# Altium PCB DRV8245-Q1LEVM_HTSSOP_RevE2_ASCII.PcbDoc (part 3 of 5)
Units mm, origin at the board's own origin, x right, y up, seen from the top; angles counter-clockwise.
Board outline 81.9 x 103.6 mm, 4 copper layers (Top Layer, Signal Layer 1, Signal Layer 2, Bottom Layer), stack 1.554 mm thick; 187 components, 116 nets, 590 pads, 1182 vias.
Unrouted connection lines stored in the file: 116.
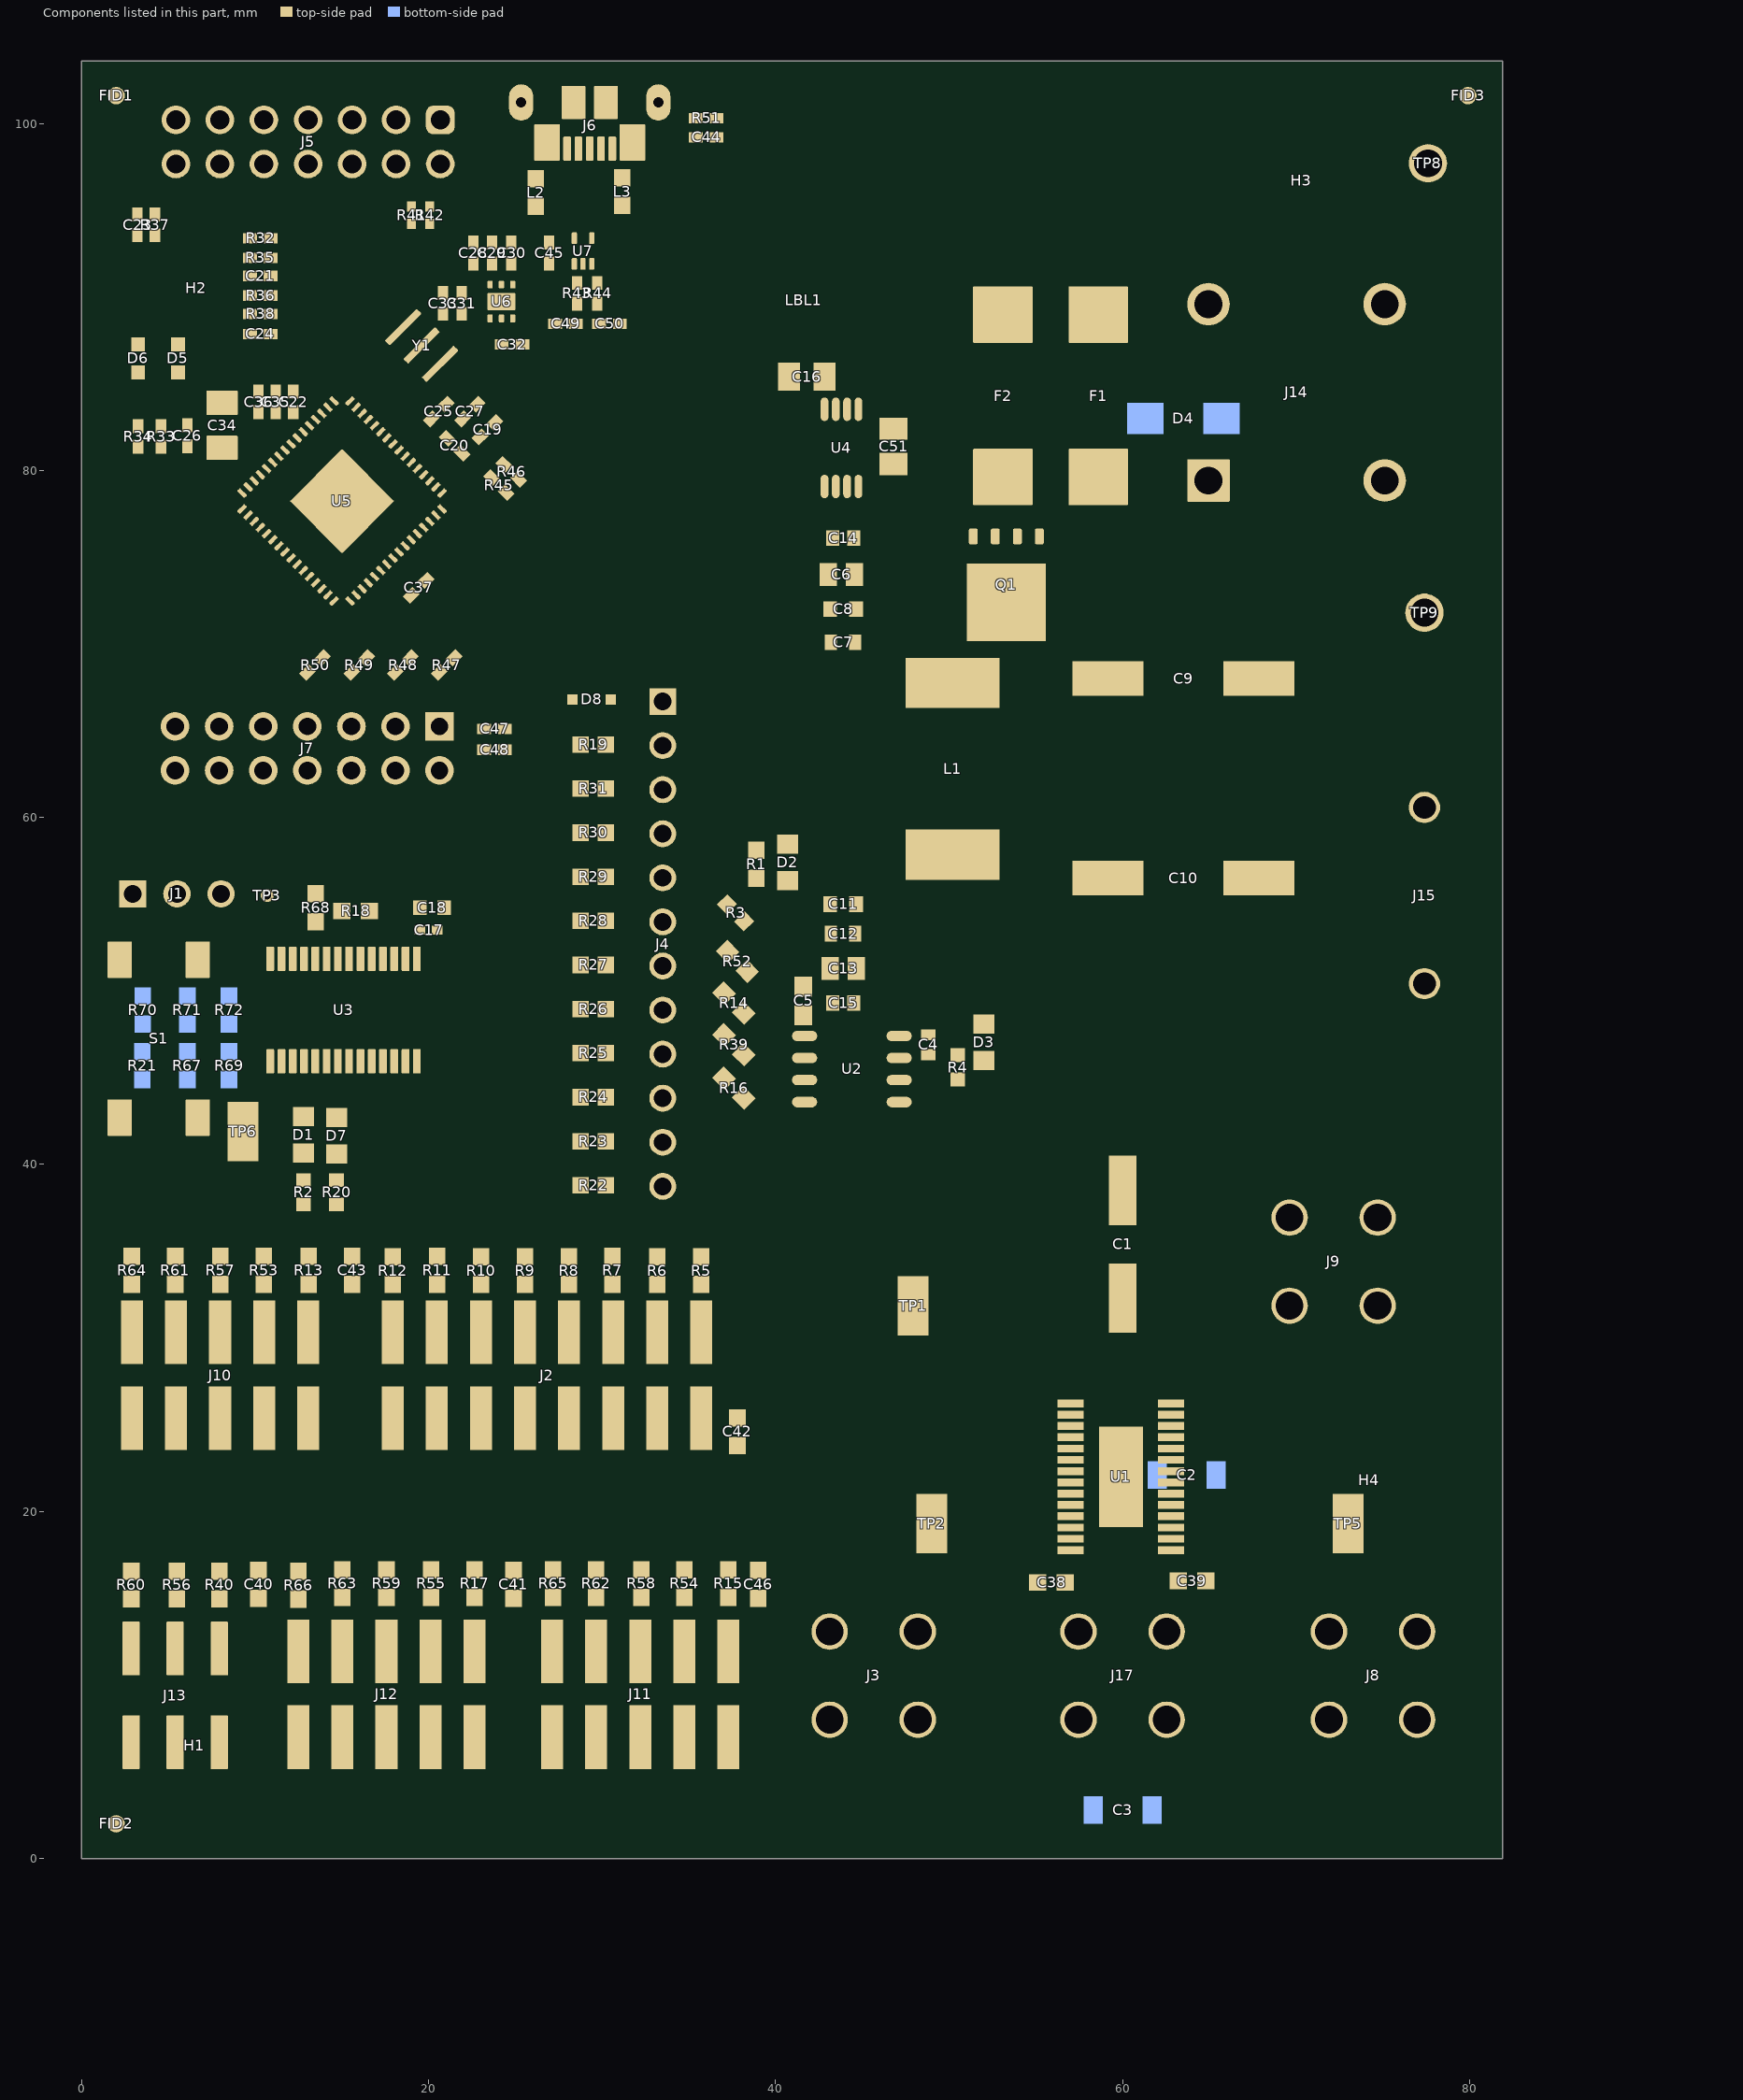
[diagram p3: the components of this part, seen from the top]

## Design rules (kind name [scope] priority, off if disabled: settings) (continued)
PolygonConnect PolygonConnect_69 [All vs IsNamedPolygon('TOP_LAYER_OUT1_P129')] p19: connectstyle=Direct reliefconductorwidth=0.254 reliefentries=4 polygonreliefangle="90 Angle" airgapwidth=0.254
PolygonConnect PolygonConnect_68 [All vs IsNamedPolygon('TOP_LAYER_VM_P085')] p20: connectstyle=Direct reliefconductorwidth=0.254 reliefentries=4 polygonreliefangle="90 Angle" airgapwidth=0.254
PolygonConnect PolygonConnect_67 [All vs IsNamedPolygon('BOTTOM_LAYER_P_IN_P174')] p21: connectstyle=Direct reliefconductorwidth=0.254 reliefentries=4 polygonreliefangle="90 Angle" airgapwidth=0.254
PolygonConnect PolygonConnect_66 [All vs IsNamedPolygon('BOTTOM_LAYER_NETF1_2_P203')] p22: connectstyle=Direct reliefconductorwidth=0.254 reliefentries=4 polygonreliefangle="90 Angle" airgapwidth=0.254
PolygonConnect PolygonConnect_65 [All vs IsNamedPolygon('BOTTOM_LAYER_VBAT_P165')] p23: connectstyle=Direct reliefconductorwidth=0.254 reliefentries=4 polygonreliefangle="90 Angle" airgapwidth=0.254
PolygonConnect PolygonConnect_64 [All vs IsNamedPolygon('TOP_LAYER_VM_P167')] p24: connectstyle=Direct reliefconductorwidth=0.254 reliefentries=4 polygonreliefangle="90 Angle" airgapwidth=0.254
PolygonConnect PolygonConnect_63 [All vs IsNamedPolygon('TOP_LAYER_VM_P167')] p25: connectstyle=Direct reliefconductorwidth=0.254 reliefentries=4 polygonreliefangle="90 Angle" airgapwidth=0.254
PolygonConnect PolygonConnect_62 [All vs IsNamedPolygon('TOP_LAYER_VM_P171')] p26: connectstyle=Direct reliefconductorwidth=0.254 reliefentries=4 polygonreliefangle="90 Angle" airgapwidth=0.254
PolygonConnect PolygonConnect_61 [All vs IsNamedPolygon('SIGNAL_LAYER_2_GND_P199')] p27: connectstyle=Direct reliefconductorwidth=0.254 reliefentries=4 polygonreliefangle="90 Angle" airgapwidth=0.254
PolygonConnect PolygonConnect_60 [All vs IsNamedPolygon('SIGNAL_LAYER_2_NETF1_2_P196')] p28: connectstyle=Direct reliefconductorwidth=0.254 reliefentries=4 polygonreliefangle="90 Angle" airgapwidth=0.254
PolygonConnect PolygonConnect_59 [All vs IsNamedPolygon('SIGNAL_LAYER_2_VBAT_P197')] p29: connectstyle=Direct reliefconductorwidth=0.254 reliefentries=4 polygonreliefangle="90 Angle" airgapwidth=0.254
PolygonConnect PolygonConnect_58 [All vs IsNamedPolygon('SIGNAL_LAYER_2_P_IN_P198')] p30: connectstyle=Direct reliefconductorwidth=0.254 reliefentries=4 polygonreliefangle="90 Angle" airgapwidth=0.254
PolygonConnect PolygonConnect_57 [All vs IsNamedPolygon('SIGNAL_LAYER_2_3V3_P194')] p31: connectstyle=Direct reliefconductorwidth=0.254 reliefentries=4 polygonreliefangle="90 Angle" airgapwidth=0.254
PolygonConnect PolygonConnect_56 [All vs IsNamedPolygon('TOP_LAYER_NETF1_2_P207')] p32: connectstyle=Direct reliefconductorwidth=0.254 reliefentries=4 polygonreliefangle="90 Angle" airgapwidth=0.254
PolygonConnect PolygonConnect_55 [All vs IsNamedPolygon('TOP_LAYER_VBAT_P223')] p33: connectstyle=Direct reliefconductorwidth=0.254 reliefentries=4 polygonreliefangle="90 Angle" airgapwidth=0.254
PolygonConnect PolygonConnect_54 [All vs IsNamedPolygon('TOP_LAYER_P_IN_P227')] p34: connectstyle=Direct reliefconductorwidth=0.254 reliefentries=4 polygonreliefangle="90 Angle" airgapwidth=0.254
PolygonConnect PolygonConnect_53 [All vs IsNamedPolygon('TOP_LAYER_GND_P086')] p35: connectstyle=Direct reliefconductorwidth=0.254 reliefentries=4 polygonreliefangle="90 Angle" airgapwidth=0.254
PolygonConnect PolygonConnect_52 [All vs IsNamedPolygon('SIGNAL_LAYER_2_VM_P177') Or  IsNamedPolygon('SIGNAL_LAYER_2_VM_P179') Or  IsNamedPolygon('SIGNAL_LAYER_2_VM_P160') Or  IsNamedPolygon('SIGNAL_LAYER_2_VM_P175') Or  IsNamedPolygon('SIGNAL_LAYER_2_VM_P181')] p36: connectstyle=Direct reliefconductorwidth=0.254 reliefentries=4 polygonreliefangle="90 Angle" airgapwidth=0.254
PolygonConnect PolygonConnect_51 [All vs IsNamedPolygon('SIGNAL_LAYER_2_EZFET_VBUS_P136')] p37: connectstyle=Direct reliefconductorwidth=0.254 reliefentries=4 polygonreliefangle="90 Angle" airgapwidth=0.254
PolygonConnect PolygonConnect_50 [All vs IsNamedPolygon('SIGNAL_LAYER_2_EZFET_VCC_P132')] p38: connectstyle=Direct reliefconductorwidth=0.254 reliefentries=4 polygonreliefangle="90 Angle" airgapwidth=0.254
PolygonConnect PolygonConnect_49 [All vs IsNamedPolygon('SIGNAL_LAYER_2_3V3_MCU_P192')] p39: connectstyle=Direct reliefconductorwidth=0.254 reliefentries=4 polygonreliefangle="90 Angle" airgapwidth=0.254
PolygonConnect PolygonConnect_48 [All vs IsNamedPolygon('SIGNAL_LAYER_1_GND_P190')] p40: connectstyle=Direct reliefconductorwidth=0.254 reliefentries=4 polygonreliefangle="90 Angle" airgapwidth=0.254
PolygonConnect PolygonConnect_47 [All vs IsNamedPolygon('SIGNAL_LAYER_1_GND_P184')] p41: connectstyle=Direct reliefconductorwidth=0.254 reliefentries=4 polygonreliefangle="90 Angle" airgapwidth=0.254
PolygonConnect PolygonConnect_46 [All vs IsNamedPolygon('BOTTOM_LAYER_GND_P241')] p42: connectstyle=Direct reliefconductorwidth=0.254 reliefentries=4 polygonreliefangle="90 Angle" airgapwidth=0.254
PolygonConnect PolygonConnect_45 [All vs IsNamedPolygon('BOTTOM_LAYER_GND_P241')] p43: connectstyle=Direct reliefconductorwidth=0.254 reliefentries=4 polygonreliefangle="90 Angle" airgapwidth=0.254
PolygonConnect PolygonConnect_44 [All vs IsNamedPolygon('BOTTOM_LAYER_OUT2_P163')] p44: connectstyle=Direct reliefconductorwidth=0.254 reliefentries=4 polygonreliefangle="90 Angle" airgapwidth=0.254
PolygonConnect PolygonConnect_43 [All vs IsNamedPolygon('BOTTOM_LAYER_VM_P166')] p45: connectstyle=Direct reliefconductorwidth=0.254 reliefentries=4 polygonreliefangle="90 Angle" airgapwidth=0.254
PolygonConnect PolygonConnect_42 [All vs IsNamedPolygon('BOTTOM_LAYER_VM_P235')] p46: connectstyle=Direct reliefconductorwidth=0.254 reliefentries=4 polygonreliefangle="90 Angle" airgapwidth=0.254
PolygonConnect PolygonConnect_41 [All vs IsNamedPolygon('BOTTOM_LAYER_OUT1_P164')] p47: connectstyle=Direct reliefconductorwidth=0.254 reliefentries=4 polygonreliefangle="90 Angle" airgapwidth=0.254
PolygonConnect PolygonConnect_40 [All vs IsNamedPolygon('BOTTOM_LAYER_GND_P162')] p48: connectstyle=Direct reliefconductorwidth=0.254 reliefentries=4 polygonreliefangle="90 Angle" airgapwidth=0.254
PolygonConnect PolygonConnect_39 [All vs IsNamedPolygon('SIGNAL_LAYER_2_VM_P160')] p49: connectstyle=Direct reliefconductorwidth=0.254 reliefentries=4 polygonreliefangle="90 Angle" airgapwidth=0.254
PolygonConnect PolygonConnect_38 [All vs IsNamedPolygon('SIGNAL_LAYER_2_NONET_P138')] p50: connectstyle=Direct reliefconductorwidth=0.254 reliefentries=4 polygonreliefangle="90 Angle" airgapwidth=0.254
PolygonConnect PolygonConnect_37 [All vs IsNamedPolygon('SIGNAL_LAYER_1_VM_P146')] p51: connectstyle=Direct reliefconductorwidth=0.254 reliefentries=4 polygonreliefangle="90 Angle" airgapwidth=0.254
PolygonConnect PolygonConnect_36 [All vs IsNamedPolygon('SIGNAL_LAYER_2_GND_P156')] p52: connectstyle=Direct reliefconductorwidth=0.254 reliefentries=4 polygonreliefangle="90 Angle" airgapwidth=0.254
PolygonConnect PolygonConnect_35 [All vs IsNamedPolygon('BOTTOM_LAYER_EZFET_USB_SHIELD_P219')] p53: connectstyle=Direct reliefconductorwidth=0.254 reliefentries=4 polygonreliefangle="90 Angle" airgapwidth=0.254
PolygonConnect PolygonConnect_34 [All vs IsNamedPolygon('SIGNAL_LAYER_1_VM_P144')] p54: connectstyle=Direct reliefconductorwidth=0.254 reliefentries=4 polygonreliefangle="90 Angle" airgapwidth=0.254
PolygonConnect PolygonConnect_33 [All vs IsNamedPolygon('SIGNAL_LAYER_1_VM_P148') Or  IsNamedPolygon('SIGNAL_LAYER_1_VM_P148')] p55: connectstyle=Direct reliefconductorwidth=0.254 reliefentries=4 polygonreliefangle="90 Angle" airgapwidth=0.254
PolygonConnect PolygonConnect_32 [All vs IsNamedPolygon('SIGNAL_LAYER_1_GND_P154')] p56: connectstyle=Direct reliefconductorwidth=0.254 reliefentries=4 polygonreliefangle="90 Angle" airgapwidth=0.254
PolygonConnect PolygonConnect_31 [All vs IsNamedPolygon('SIGNAL_LAYER_2_NONET_P138')] p57: connectstyle=Direct reliefconductorwidth=0.254 reliefentries=4 polygonreliefangle="90 Angle" airgapwidth=0.254
PolygonConnect PolygonConnect_30 [All vs IsNamedPolygon('SIGNAL_LAYER_2_GND_P082')] p58: connectstyle=Direct reliefconductorwidth=0.254 reliefentries=4 polygonreliefangle="90 Angle" airgapwidth=0.254
PolygonConnect PolygonConnect_29 [All vs IsNamedPolygon('TOP_LAYER_GND_P076')] p59: connectstyle=Direct reliefconductorwidth=0.254 reliefentries=4 polygonreliefangle="90 Angle" airgapwidth=0.254
PolygonConnect PolygonConnect_28 [All vs IsNamedPolygon('TOP_LAYER_GND_P087')] p60: connectstyle=Direct reliefconductorwidth=0.254 reliefentries=4 polygonreliefangle="90 Angle" airgapwidth=0.254
PolygonConnect PolygonConnect_27 [All vs IsNamedPolygon('TOP_LAYER_VM_P127') Or  IsNamedPolygon('TOP_LAYER_VM_P085')] p61: connectstyle=Direct reliefconductorwidth=0.254 reliefentries=4 polygonreliefangle="90 Angle" airgapwidth=0.254
PolygonConnect PolygonConnect_26 [All vs IsNamedPolygon('TOP_LAYER_GND_P117')] p62: connectstyle=Direct reliefconductorwidth=0.254 reliefentries=4 polygonreliefangle="90 Angle" airgapwidth=0.254
PolygonConnect PolygonConnect_25 [All vs IsNamedPolygon('TOP_LAYER_OUT1_P129') Or  IsNamedPolygon('TOP_LAYER_OUT2_P173')] p63: connectstyle=Direct reliefconductorwidth=0.254 reliefentries=4 polygonreliefangle="90 Angle" airgapwidth=0.254
PolygonConnect PolygonConnect_24 [All vs IsNamedPolygon('SIGNAL_LAYER_2_NONET_P113')] p64: connectstyle=Direct reliefconductorwidth=0.254 reliefentries=4 polygonreliefangle="90 Angle" airgapwidth=0.254
PolygonConnect PolygonConnect_23 [All vs IsNamedPolygon('BOTTOM_LAYER_NONET_P115')] p65: connectstyle=Direct reliefconductorwidth=0.254 reliefentries=4 polygonreliefangle="90 Angle" airgapwidth=0.254
PolygonConnect PolygonConnect_22 [All vs IsNamedPolygon('SIGNAL_LAYER_1_NONET_P111')] p66: connectstyle=Direct reliefconductorwidth=0.254 reliefentries=4 polygonreliefangle="90 Angle" airgapwidth=0.254
PolygonConnect PolygonConnect_21 [All vs IsNamedPolygon('TOP_LAYER_NONET_P083')] p67: connectstyle=Direct reliefconductorwidth=0.254 reliefentries=4 polygonreliefangle="90 Angle" airgapwidth=0.254
PolygonConnect PolygonConnect_20 [All vs IsNamedPolygon('TOP_LAYER_NONET_P105')] p68: connectstyle=Direct reliefconductorwidth=0.254 reliefentries=4 polygonreliefangle="90 Angle" airgapwidth=0.254
PolygonConnect PolygonConnect_19 [All vs IsNamedPolygon('TOP_LAYER_OUT2_P107')] p69: connectstyle=Direct reliefconductorwidth=0.254 reliefentries=4 polygonreliefangle="90 Angle" airgapwidth=0.254
PolygonConnect PolygonConnect_18 [All vs IsNamedPolygon('TOP_LAYER_NONET_P101')] p70: connectstyle=Direct reliefconductorwidth=0.254 reliefentries=4 polygonreliefangle="90 Angle" airgapwidth=0.254
PolygonConnect PolygonConnect_17 [All vs IsNamedPolygon('TOP_LAYER_OUT1_P103')] p71: connectstyle=Direct reliefconductorwidth=0.254 reliefentries=4 polygonreliefangle="90 Angle" airgapwidth=0.254
PolygonConnect PolygonConnect_16 [All vs IsNamedPolygon('TOP_LAYER_OUT1_P000')] p72: connectstyle=Direct reliefconductorwidth=0.254 reliefentries=4 polygonreliefangle="90 Angle" airgapwidth=0.254
PolygonConnect PolygonConnect_15 [All vs IsNamedPolygon('TOP_LAYER_NONET_P093')] p73: connectstyle=Direct reliefconductorwidth=0.254 reliefentries=4 polygonreliefangle="90 Angle" airgapwidth=0.254
PolygonConnect PolygonConnect_14 [All vs IsNamedPolygon('TOP_LAYER_OUT2_P099')] p74: connectstyle=Direct reliefconductorwidth=0.254 reliefentries=4 polygonreliefangle="90 Angle" airgapwidth=0.254
PolygonConnect PolygonConnect_13 [All vs IsNamedPolygon('TOP_LAYER_OUT1_P000')] p75: connectstyle=Direct reliefconductorwidth=0.254 reliefentries=4 polygonreliefangle="90 Angle" airgapwidth=0.254
PolygonConnect PolygonConnect_12 [All vs IsNamedPolygon('BOTTOM_LAYER_NONET_P079') Or  IsNamedPolygon('SIGNAL_LAYER_2_NONET_P078') Or  IsNamedPolygon('SIGNAL_LAYER_1_NONET_P077') Or  IsNamedPolygon('TOP_LAYER_NONET_P083') Or  IsNamedPolygon('BOTTOM_LAYER_NONET_P072') Or  IsNamedPolygon('SIGNAL_LAYER_2_NONET_P070') Or  IsNamedPolygon('SIGNAL_LAYER_1_NONET_P059') Or  IsNamedPolygon('TOP_LAYER_OUT2_P058') Or  IsNamedPolygon('BOTTOM_LAYER_NONET_P056') Or  IsNamedPolygon('SIGNAL_LAYER_2_NONET_P054') Or  IsNamedPolygon('SIGNAL_LAYER_1_NONET_P052') Or  IsNamedPolygon('TOP_LAYER_OUT1_P050') Or  IsNamedPolygon('BOTTOM_LAYER_VM_P044') Or  IsNamedPolygon('SIGNAL_LAYER_2_VM_P042') Or  IsNamedPolygon('SIGNAL_LAYER_1_VM_P040') Or  IsNamedPolygon('TOP_LAYER_VM_P038') Or  IsNamedPolygon('BOTTOM_LAYER_VM_P036') Or  IsNamedPolygon('SIGNAL_LAYER_2_VM_P018') Or  IsNamedPolygon('SIGNAL_LAYER_1_VM_P016') Or  IsNamedPolygon('TOP_LAYER_VM_P002')] p76: connectstyle=Direct reliefconductorwidth=0.254 reliefentries=4 polygonreliefangle="90 Angle" airgapwidth=0.254
PolygonConnect PolygonConnect_11 [All vs IsNamedPolygon('TOP_LAYER_NONET_P089') Or  IsNamedPolygon('TOP_LAYER_NONET_P090')] p77: connectstyle=Direct reliefconductorwidth=0.254 reliefentries=4 polygonreliefangle="90 Angle" airgapwidth=0.254
PolygonConnect PolygonConnect_10 [All vs IsNamedPolygon('BOTTOM_LAYER_EZFET_USB_SHIELD_P002') Or  IsNamedPolygon('TOP_LAYER_EZFET_USB_SHIELD_P201') Or  IsNamedPolygon('SIGNAL_LAYER_2_EZFET_VBUS_P018') Or  IsNamedPolygon('SIGNAL_LAYER_2_EZFET_VCC_P016')] p78: connectstyle=Direct reliefconductorwidth=0.254 reliefentries=4 polygonreliefangle="90 Angle" airgapwidth=0.254
PolygonConnect PolygonConnect_9 [All vs IsNamedPolygon('TOP_LAYER_VM_P123') Or  IsNamedPolygon('TOP_LAYER_VM_P123') Or  IsNamedPolygon('TOP_LAYER_VM_P123')] p79: connectstyle=Direct reliefconductorwidth=0.254 reliefentries=4 polygonreliefangle="90 Angle" airgapwidth=0.254
PolygonConnect PolygonConnect_8 [All vs IsNamedPolygon('TOP_LAYER_NONET_P072')] p80: connectstyle=Direct reliefconductorwidth=0.254 reliefentries=4 polygonreliefangle="90 Angle" airgapwidth=0.254
PolygonConnect PolygonConnect_7 [All vs IsNamedPolygon('TOP_LAYER_NONET_P072')] p81: connectstyle=Direct reliefconductorwidth=0.254 reliefentries=4 polygonreliefangle="90 Angle" airgapwidth=0.254
PolygonConnect PolygonConnect_6 [All vs IsNamedPolygon('TOP_LAYER_VM_P042')] p82: connectstyle=Direct reliefconductorwidth=0.254 reliefentries=4 polygonreliefangle="90 Angle" airgapwidth=0.254
PolygonConnect PolygonConnect_5 [All vs IsNamedPolygon('TOP_LAYER_VM_P044')] p83: connectstyle=Direct reliefconductorwidth=0.254 reliefentries=4 polygonreliefangle="90 Angle" airgapwidth=0.254
PolygonConnect PolygonConnect_4 [All vs IsNamedPolygon('TOP_LAYER_VM_P046')] p84: connectstyle=Direct reliefconductorwidth=0.254 reliefentries=4 polygonreliefangle="90 Angle" airgapwidth=0.254
PolygonConnect PolygonConnect_3 [All vs IsNamedPolygon('TOP_LAYER_GND_P036') Or  IsNamedPolygon('TOP_LAYER_OUT2_P040') Or  IsNamedPolygon('TOP_LAYER_OUT1_P038')] p85: connectstyle=Direct reliefconductorwidth=0.254 reliefentries=4 polygonreliefangle="90 Angle" airgapwidth=0.254
PolygonConnect PolygonConnect_2 [InNet('EZFET_VBUS') vs IsNamedPolygon('TOP_LAYER_EZFET_VBUS_P008')] p86: connectstyle=Direct reliefconductorwidth=0.254 reliefentries=4 polygonreliefangle="90 Angle" airgapwidth=0.254
PolygonConnect PolygonConnect_1 [InNetClass('Power-Net') vs IsNamedPolygon('TOP_LAYER_EZFET_USB_SHIELD_P201')] p87: connectstyle=Direct reliefconductorwidth=0.254 reliefentries=4 polygonreliefangle="90 Angle" airgapwidth=0.254
PolygonConnect [All] p88: connectstyle=Relief reliefconductorwidth=0.254 reliefentries=4 polygonreliefangle="90 Angle" airgapwidth=0.254
RoutingCorners [All] p0: scope1count=1 scope1_0_kind=Board scope1_0_value=Board scope2count=1 scope2_0_kind=Board scope2_0_value=Board commentlength=0 cornerstyle=45-Degree minsetback=2.54 maxsetback=2.54
RoutingLayers [All] p0: scope1count=1 scope1_0_kind=Board scope1_0_value=Board scope2count=1 scope2_0_kind=Board scope2_0_value=Board commentlength=0 top layer=Automatic mid layer 1=Automatic mid layer 2=Automatic bottom layer=Automatic
RoutingPriority [All] p0: scope1count=1 scope1_0_kind=Board scope1_0_value=Board scope2count=1 scope2_0_kind=Board scope2_0_value=Board commentlength=0
RoutingTopology [All] p0: scope1count=1 scope1_0_kind=Board scope1_0_value=Board scope2count=1 scope2_0_kind=Board scope2_0_value=Board commentlength=0 topology=Shortest
RoutingVias [All] p0: scope1count=1 scope1_0_kind=Board scope1_0_value=Board scope2count=1 scope2_0_kind=Board scope2_0_value=Board commentlength=0 holewidth=0.406 width=0.864 viastyle="Through Hole" minholewidth=0.2 minwidth=0.66 maxholewidth=1.016 maxwidth=1.651
RoutingVias ThermalPadVias [All] p0 off: scope1count=1 scope1_0_kind=Board scope1_0_value=Board scope2count=1 scope2_0_kind=Board scope2_0_value=Board commentlength=63 holewidth=0.2 width=0.5 viastyle="Through Hole" minholewidth=0.2 minwidth=0.5 maxholewidth=0.33 maxwidth=0.6 // Protel DXP Scope 1 Expression Was: IsVia and InAnyComponent
RoutingVias ThermalPadVias [IsVia and InAnyComponent] p1: holewidth=0.2 width=0.5 viastyle="Through Hole" minholewidth=0.2 minwidth=0.5 maxholewidth=0.33 maxwidth=0.6
RoutingVias [All] p2: holewidth=0.406 width=0.864 viastyle="Through Hole" minholewidth=0.2 minwidth=0.66 maxholewidth=1.016 maxwidth=1.651
ShortCircuit [All] p0: scope1count=1 scope1_0_kind=Board scope1_0_value=Board scope2count=1 scope2_0_kind=Board scope2_0_value=Board commentlength=0 allowed=FALSE
SilkToBoardRegionClearance [All] p0 off: scope1count=1 scope1_0_kind=Board scope1_0_value=Board scope2count=1 scope2_0_kind=Board scope2_0_value=Board commentlength=130 // Protel DXP Scope 1 Expression Was: Not ((IsComment or IsDesignator) And (Hide <> 'False')) and not InRegion(1000,500,4000,800)
SilkToBoardRegionClearance [Not ((IsComment or IsDesignator) And (Hide <> 'False')) and not InRegion(1000,500,4000,800)] p1:
SilkToSilkClearance [All] p0: scope1count=1 scope1_0_kind=Board scope1_0_value=Board scope2count=1 scope2_0_kind=Board scope2_0_value=Board commentlength=0
SilkToSilkClearance SilkToSilkClearance_Pb-FreeLogo [All] p0 off: scope1count=1 scope1_0_kind=Board scope1_0_value=Board scope2count=1 scope2_0_kind=Board scope2_0_value=Board commentlength=120 // Protel DXP Scope 2 Expression Was: (HasFootprint('Pb-Free_Overlay_Medium') OR HasFootprint('Pb-Free_Overlay_Small'))
SilkToSilkClearance SilkToSilkClearance_Pb-FreeLogo [(HasFootprint('Pb-Free_Overlay_Medium') OR HasFootprint('Pb-Free_Overlay_Small')) vs (HasFootprint('Pb-Free_Overlay_Medium') OR HasFootprint('Pb-Free_Overlay_Small'))] p1: silktosilkclearance=0
SilkToSilkClearance [All] p2: silktosilkclearance=0.1
SilkToSolderMaskClearance "Silk to Solder Mask Opening" [All] p0: scope1count=1 scope1_0_kind=Board scope1_0_value=Board scope2count=1 scope2_0_kind=Board scope2_0_value=Board commentlength=0
SilkToSolderMaskClearance SilkToComponentPadClearance [All] p0 off: scope1count=1 scope1_0_kind=Board scope1_0_value=Board scope2count=1 scope2_0_kind=Board scope2_0_value=Board commentlength=87 // Protel DXP Scope 1 Expression Was: (IsPad or IsFill or IsRegion) and InAnycomponent
SilkToSolderMaskClearance SilkToComponentPadClearance [(IsPad or IsFill or IsRegion) and InAnycomponent] p1: minsilkscreentomaskgap=0.127 clearancetoexposedcopper=TRUE
SilkToSolderMaskClearance "Silk to Solder Mask Opening" [All] p2: minsilkscreentomaskgap=0.1 clearancetoexposedcopper=FALSE
SolderMaskExpansion [All] p0: scope1count=1 scope1_0_kind=Board scope1_0_value=Board scope2count=1 scope2_0_kind=Board scope2_0_value=Board commentlength=0 expansion=0.05
SolderMaskExpansion [All] p1: expansion=0.05
UnRoutedNet [All] p0: scope1count=1 scope1_0_kind=Board scope1_0_value=Board scope2count=1 scope2_0_kind=Board scope2_0_value=Board commentlength=0
UnRoutedNet [All] p1: checkbadconnections=TRUE
UnpouredPolygon [All] p0: scope1count=1 scope1_0_kind=Board scope1_0_value=Board scope2count=1 scope2_0_kind=Board scope2_0_value=Board commentlength=0
Width [All] p0: scope1count=1 scope1_0_kind=Board scope1_0_value=Board scope2count=1 scope2_0_kind=Board scope2_0_value=Board commentlength=0 maxlimit=2.54 minlimit=0.152 preferedwidth=0.254
Width [All] p1: maxlimit=2.54 minlimit=0.152 preferedwidth=0.254 checkconnectedcopper=TRUE
14 further rules are at their usual default settings.

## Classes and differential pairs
net class Power-Net: 3V3_MCU EZFET_VBUS EZFET_VCC GND
component class Header: J2 J4 J5 J7 J10 J11 J12 J13
component class ezFET: C19 C20 C21 C22 C23 C24 C25 C26 C27 C28 C29 C30 C31 C32 C33 C34 C35 C36 C37 C44 C45 C47 C48 C49 C50 D5 D6 J5 J6 J7 L2 L3 R32 R33 R34 R35 R36 R37 R38 R41 R42 R43 R44 R45 R46 R47 R48 R49 R50 R51 U5 U6 U7 Y1
component class Logo: Logo2
component class FiducialMark: FID1 FID2 FID3
component class AssemblyNote: ZZ1 ZZ2 ZZ3 ZZ4
component class Label: LBL1
differential pair USB_D: +USB_D_P -USB_D_N
differential pair " ": +EZFET_D_P -EZFET_D_N

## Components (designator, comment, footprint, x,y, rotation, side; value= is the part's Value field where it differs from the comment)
C1 "EEE-2AA100UP" SM_RADIAL_E 60,35.4 r270 top
C2 "C3216X7R2A104K160AA" 1206_180 63.7,22.1 r180 bottom
C3 "C3216X7R2A104K160AA" 1206_180 60,2.8 r0 bottom
C4 "CL10B104JB8NNNC" FP-CL10-0_1-MFG 48.8,46.9 r270 top
C5 "CL10A226MQ8NUNE" FP-CL10-IPC_A 41.6,49.427 r90 top
C6 "1uF" CAPC2013X135X45LL10T25 43.8,74 r0 top
C7 "0.1uF" CAPC0603(1608)100_L 43.9,70.1 r0 top
C8 "CC0603KPX7R9BB103" FP-CC0603-DA-MFG 43.9,72 r0 top
C9 "EEE-FK1H151P" SM_RADIAL_G 63.5,68 r0 top
C10 "EEE-FK1H151P" SM_RADIAL_G 63.5,56.5 r0 top
C11 "CC0603KPX7R9BB103" FP-CC0603-DA-MFG 43.9,55 r180 top
C12 "0.1uF" CAPC0603(1608)100_L 43.9,53.3 r0 top
C13 "1uF" CAPC2013X135X45LL10T25 43.9,51.3 r0 top
C14 "1nF" FP-C0603C-CF-MFG#1 44,76.1 r180 top
C15 "1nF" FP-C0603C-CF-MFG#2 43.9,49.3 r180 top
C16 "08055A101JAT2A" 0805_HV 41.8,85.4 r180 top
C17 "Capacitor" 0402_065L 20,53.5 r0 top
C18 "885012206020" 0603L 20.2,54.8 r0 top
C19 "C1005X5R1A475M050BC" 0402 23.397,82.347 r45 top
C20 "GRM155R61A104KA01D" 0402 21.501,81.429 r315 top
C21 "C1005C0G1H330J050BA" 0402 10.302,91.208 r180 top
C22 "GRM155R61A104KA01D" 0402 12.2,83.95 r90 top
C23 "GRM155R71H102KA01D" 0402 3.228,94.149 r270 top
C24 "C1005C0G1H330J050BA" 0402 10.302,87.856 r180 top
C25 "GRM155R61A224KE19D" 0402 20.583,83.39 r45 top
C26 "GRM155R61C474KE01" 0402 6.1,82 r90 top
C27 "GRM155R61A224KE19D" 0402 22.382,83.39 r45 top
C28 "885012105012" 0402 22.577,92.525 r90 top
C29 "GRM155R61A104KA01D" 0402 23.655,92.525 r90 top
C30 "GRM155R71C103KA01D" 0402 24.774,92.525 r90 top
C31 "2.2uF" 0402 21.905,89.625 r90 top
C32 "GRM155R71C103KA01D" 0402 24.814,87.256 r0 top
C33 "885012105012" 0402 20.831,89.625 r90 top
C34 "T520A106M010ATE080" 3216-18 8.1,82.6 r90 top
C35 "GRM155R61A104KA01D" 0402 11.19,83.95 r90 top
C36 "GRM155R61A104KA01D" 0402 10.205,83.95 r90 top
C37 "GRM155R61A104KA01D" 0402 19.43,73.233 r225 top
C38 "CGA3E2X7R2A102K080AA" 0603 55.9,15.9 r180 top
C39 "CGA3E2X7R2A102K080AA" 0603 64,16 r0 top
C40 "CGA3E2X7R2A102K080AA" 0603 10.2,15.8 r270 top
C41 "CGA3E2X7R2A102K080AA" 0603 24.9,15.8 r270 top
C42 "CGA3E2X7R2A102K080AA" 0603 37.8,24.6 r90 top
C43 "CGA3E2X7R2A102K080AA" 0603 15.6,33.9 r270 top
C44 "GRM155R61A224KE19D" 0402 36,99.2 r0 top
C45 "GRM155R61A104KA01D" 0402 26.955,92.525 r90 top
C46 "CGA3E2X7R2A102K080AA" 0603 39,15.8 r270 top
C47 "GRM1555C1H100FA01D" 0402 23.8,65.1 r180 top
C48 "GRM1555C1H100FA01D" 0402 23.8,63.9 r180 top
C49 "GRM1555C1H100FA01D" 0402 27.891,88.458 r180 top
C50 "GRM1555C1H100FA01D" 0402 30.429,88.458 r0 top
C51 "C2012X5R1H225K125AB" 0805_HV 46.8,81.384 r90 top
D1 "150080VS75000" 0805_A 12.8,41.7 r90 top
D2 "150080SS75000" 0805_A 40.7,57.4 r90 top
D3 "150080VS75000" 0805_A 52,47.05 r90 top
D4 "SMAJ36CA" FP-SMAJ-CA-MFG 63.5,83 r180 bottom
D5 "150060RS75000" WL-SMCW_RED 5.561,86.456 r270 top
D6 "CMP-0002894-2" WL-SMCW_GREEN 3.258,86.456 r270 top
D7 "150080VS75000" 0805_A 14.7,41.65 r90 top
D8 "BAT165E6327HTSA1" SOD-323 29.4,66.8 r180 top
F1 "0463030.ER" Fuse_0463 58.6,84.3 r90 top
F2 "0463030.ER" Fuse_0463 53.1,84.3 r90 top
FID1 "Fiducial" Fiducial10-20 2,101.6 r0 top
FID2 "Fiducial" Fiducial10-20 2,2 r90 top
FID3 "Fiducial" Fiducial10-20 79.9,101.6 r0 top
H1 "SJ-5303 (CLEAR)" Bumpon_SJ5003Transparent 6.5,6.5 r0 bottom
H2 "SJ-5303 (CLEAR)" Bumpon_SJ5003Transparent 6.6,90.5 r0 bottom
H3 "SJ-5303 (CLEAR)" Bumpon_SJ5003Transparent 70.3,96.7 r0 bottom
H4 "SJ-5303 (CLEAR)" Bumpon_SJ5003Transparent 74.2,21.8 r180 bottom
J1 "PR20203VBNN" FP-PR20203VBNN-MFG 5.5,55.6 r0 top
J2 "TSM-108-01-L-DV" Samtec_TSM-108-01-x-DV 26.832,27.851 r270 top
J3 "CT3151SP-2" CTE_CT3151SP-2 45.66,-10.898 r90 top
J4 "PBC12SABN" Sullins_PxC12SABN 33.5,52.71 r270 top
J5 "61301421121" Wurth_61301421121 13.056,98.93 r270 top
J6 "CMP-0055311-1" Molex_1051640001 29.291,102.654 r180 top
J7 "PEC07DAAN" CONN_PEC07DAAN 13.015,63.978 r180 top
J8 "CT3151SP-2" CTE_CT3151SP-2 74.44,-10.898 r90 top
J9 "CT3151SP-2" CTE_CT3151SP-2 93.6,34.4 r180 top
J10 "TSM-105-01-L-DV-P" Samtec_TSM-105-01-x-DV 7.99,27.851 r270 top
J11 "TSM-105-01-L-DV-P" Samtec_TSM-105-01-x-DV 32.204,9.465 r270 top
J12 "TSM-105-01-L-DV-P" Samtec_TSM-105-01-x-DV 17.577,9.465 r270 top
J13 "61000621121" Wurth_61000621121 5.4,9.4 r270 top
J14 "691256610002" FP-691256610002_HDR2-MFG 72.5,84.5 r90 top
J15 "D3082-05" Harwin_D3082-05 77.4,55.5 r90 top
J17 "CT3151SP-0" CTE_CT3151SP-0 60,-10.898 r90 top
L1 "1uH" WE-HCC-1210 50.2,62.8 r270 top
L2 "BLM18AG151BH1D" 0603 26.174,96.01 r270 top
L3 "BLM18AG151BH1D" 0603 31.154,96.066 r270 top
LBL1 "THT-14-423-10" Label_650x200 41.6,89.8 r0 top
Logo1 "CE Mark" CE_Mark_5mm 33.6,84 r180 bottom
Logo2 "Texas Instruments" TI_Stacked_Overlay_Small 55.2,99 r0 top
Logo3 "FCC disclaimer" FCC_disclaimer -79.62,84.1 r270 bottom
Logo4 "WEEE logo" WEEE_Minimum 33.7,76.8 r180 bottom
Logo5 "CAUTION.  READ USER GUIDE BEFORE USE" IEC_Caution_Small 60.4,47.9 r0 top
LOGO6 "CAUTION HOT SURFACE" IEC_HotSurface_Small 52.2,26.1 r0 top
Q1 "CSD18513Q5A" DQJ0008A 53.3,73.4 r270 top
R1 "RC0603JR-0710KL" 0603 38.9,57.3 r90 top
R2 "CMP-0025785-4" 0603L 12.8,38.4 r90 top
R3 "CMP-0025785-4" 0603L 37.7,54.5 r315 top
R4 "CRCW06034K99FKEAC" 0603L 50.5,45.6 r270 top
R5 "RC0603FR-07470RL" 0603 35.722,33.882 r270 top
R6 "RC0603FR-07680RL" 0603 33.182,33.882 r270 top
R7 "RC0603FR-071KL" 0603 30.6,33.9 r270 top
R8 "RC0603FR-071K5L" 0603 28.102,33.882 r270 top
R9 "RC0603FR-072K2L" 0603 25.562,33.882 r270 top
R10 "RC0603FR-073K3L" 0603 23.022,33.882 r270 top
R11 "RC0603FR-074K7L" 0603 20.5,33.9 r270 top
R12 "RC0603FR-076K8L" 0603 17.942,33.882 r270 top
R13 "PMR03EZPJ000" 0603 13.1,33.9 r90 top
R14 "PMR03EZPJ000" 0603 37.6,49.3 r135 top
R15 "PMR03EZPJ000" 0603 37.284,15.846 r90 top
R16 "PMR03EZPJ000" 0603 37.6,44.4 r135 top
R17 "PMR03EZPJ000" 0603 22.657,15.846 r90 top
R18 "RC0603JR-0747KL" 0603 15.8,54.6 r180 top
R19 "CRCW06030000Z0EAHP" RESC1609X55X30NL10T20 29.5,64.2 r0 top
R20 "CMP-0025785-4" 0603L 14.7,38.4 r90 top
R21 "RC0603JR-0710KL" 0603 3.5,45.7 r90 bottom
R22 "CRCW06030000Z0EAHP" RESC1609X55X30NL10T20 29.5,38.8 r0 top
R23 "CRCW06030000Z0EAHP" RESC1609X55X30NL10T20 29.5,41.34 r0 top
R24 "CRCW06030000Z0EAHP" RESC1609X55X30NL10T20 29.5,43.88 r0 top
R25 "CRCW06030000Z0EAHP" RESC1609X55X30NL10T20 29.5,46.42 r0 top
R26 "CRCW06030000Z0EAHP" RESC1609X55X30NL10T20 29.5,48.96 r0 top
R27 "CRCW06030000Z0EAHP" RESC1609X55X30NL10T20 29.5,51.5 r0 top
R28 "CRCW06030000Z0EAHP" RESC1609X55X30NL10T20 29.5,54.04 r0 top
R29 "CRCW06030000Z0EAHP" RESC1609X55X30NL10T20 29.5,56.58 r0 top
R30 "CRCW06030000Z0EAHP" RESC1609X55X30NL10T20 29.5,59.12 r0 top
R31 "CRCW06030000Z0EAHP" RESC1609X55X30NL10T20 29.5,61.66 r0 top
R32 "CRCW0402240KFKED" 0402 10.314,93.383 r180 top
R33 "CRCW0402470RJNED" 0402 4.578,81.956 r270 top
R34 "CRCW0402390RJNED" 0402 3.258,81.956 r270 top
R35 "CRCW0402150KFKED" 0402 10.302,92.252 r0 top
R36 "RC0402FR-07220KL" 0402 10.305,90.081 r180 top
R37 "CRCW040247K0JNED" 0402 4.228,94.149 r270 top
R38 "RC0402FR-07220KL" 0402 10.305,89.02 r0 top
R39 "PMR03EZPJ000" 0603 37.6,46.9 r135 top
R40 "PMR03EZPJ000" 0603 7.95,15.761 r90 top
R41 "ERJ-2GE0R00X" 0402L 19.011,94.708 r90 top
R42 "ERJ-2GE0R00X" 0402L 20.062,94.708 r90 top
R43 "CRCW040227R0JNED" 0402 28.559,90.208 r270 top
R44 "CRCW040227R0JNED" 0402 29.728,90.208 r270 top
R45 "CRCW04021K40FKED" 0402 24.051,79.155 r315 top
R46 "CRCW04021M00JNED" 0402 24.774,79.918 r135 top
R47 "CRCW040210R0FKED" 0402 21.043,68.782 r225 top
R48 "CRCW040210R0FKED" 0402 18.519,68.782 r225 top
R49 "CRCW040210R0FKED" 0402 16.003,68.783 r225 top
R50 "CRCW040210R0FKED" 0402 13.455,68.782 r225 top
R51 "CRCW040233K0JNED" 0402 36,100.3 r180 top
R52 "PMR03EZPJ000" 0603 37.8,51.7 r135 top
R53 "CRCW06038K20JNEA" 0603 10.5,33.9 r270 top
R54 "CRCW06038K20JNEA" 0603 34.744,15.846 r270 top
R55 "CRCW06038K20JNEA" 0603 20.147,15.846 r270 top
R56 "CRCW06038K20JNEA" 0603 5.501,15.761 r270 top
R57 "CRCW060322K0JNEA" 0603 8,33.9 r270 top
R58 "CRCW060322K0JNEA" 0603 32.265,15.846 r270 top
R59 "CRCW060322K0JNEA" 0603 17.577,15.846 r270 top
R60 "CRCW060382K0JNEA" 0603 2.87,15.761 r90 top
R61 "CRCW060347K0FKEA" 0603 5.4,33.9 r270 top
R62 "CRCW060347K0FKEA" 0603 29.664,15.846 r270 top
R63 "CRCW060347K0FKEA" 0603 15.037,15.846 r270 top
R64 "CRCW0603100KDHEAP" 0603 2.9,33.9 r270 top
R65 "CRCW0603100KDHEAP" 0603 27.176,15.846 r270 top
R66 "CRCW0603100KDHEAP" 0603 12.497,15.751 r270 top
R67 "RC0603JR-0710KL" 0603 6.1,45.7 r90 bottom
R68 "RC0603JR-0710KL" 0603 13.5,54.8 r270 top
R69 "RC0603JR-0710KL" 0603 8.5,45.7 r90 bottom
R70 "RC0603JR-0710KL" 0603 3.521,48.9 r90 bottom
R71 "RC0603JR-0710KL" 0603 6.1,48.9 r90 bottom
R72 "RC0603JR-0710KL" 0603 8.5,48.9 r90 bottom
S1 "FSM4JSMA" SW_FSM4JSMA 4.45,47.25 r0 top
TP1 "5015" Testpoint_Keystone_Miniature 47.93,31.85 r270 top
TP2 "5015" Testpoint_Keystone_Miniature 49,19.3 r270 top
TP3 "TP_H0.45P0.75" TP_H045P075 10.7,55.5 r90 top
TP5 "5015" Testpoint_Keystone_Miniature 73,19.3 r90 top
TP6 "5015" Testpoint_Keystone_Miniature 9.3,41.9 r90 top
TP8 "5010" Keystone5010 77.6,97.7 r180 top
TP9 "5011" Keystone5011 77.4,71.8 r0 top
U1 "DRV8245S-Q1" HTSSOP-28-epod 57,26.225 r0 top
U2 "LM9036M-3.3/NOPB" D0008A_N 44.4,45.5 r0 top
U3 "MSP430G2553IPW28R" PW0028A_N 15.1,48.9 r270 top
U4 "LM74610QDGKRQ1" DGK0008A_N 43.8,81.3 r270 top
U5 "CMP-0039269-4" RGC0064B 15.016,78.233 r315 top
U6 "TPS73533DRVR" DRV0006A 24.201,89.734 r90 top
U7 "TPD2E001DRLR" DRL0005A 28.903,92.643 r90 top
Y1 "CSTNR4M00GH5L000R0" MuRata_CSTNR 19.6,87.2 r135 top
ZZ1 "This Assembly Note is for PCB labels only" AssemblyNoteLabel 4.411,120.725 r0 top
ZZ2 "These assemblies are ESD sensitive, ESD precautions shall be observed." AssemblyNote 4.411,117.959 r0 top
ZZ3 "These assemblies must be clean and free from flux and all contaminants. Use of no clean flux is not acceptable." AssemblyNote 4.411,115.71 r0 top
ZZ4 "These assemblies must comply with workmanship standards IPC-A-610 Class 2, unless otherwise specified." AssemblyNote 4.411,113.461 r0 top

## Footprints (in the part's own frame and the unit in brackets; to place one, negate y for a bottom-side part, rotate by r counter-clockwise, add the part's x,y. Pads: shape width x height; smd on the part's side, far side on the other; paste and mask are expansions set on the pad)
0402 [mm] "0402 from SM-752 data"
  rect 0.8x0.6 smd: 1(-0.6,0) 2(0.6,0)
  silkscreen extent -1.22,-0.52 1.22,0.52
0402_065L [mm] "0402"
  rect 0.6x0.5 smd: 1(-0.5,0) 2(0.5,0)
0402L [mm] "0402 from SM-752 data"
  rect 0.6x0.5 smd: 1(-0.5,0) 2(0.5,0)
0603 [mm] "0603 from SM-752 data"
  rect 1x0.95 smd: 1(-0.8,0) 2(0.8,0)
  silkscreen extent -1.52,-0.69 1.52,0.69
0603L [mm] "0603 from SM-752 data"
  rect 0.8x0.85 smd: 1(-0.7,0) 2(0.7,0)
  silkscreen extent -0.07,-0.33 0.07,0.33
0805_A [mm] "Chip LED, 2-Leads, Body 2.0x1.3mm, IPC Medium Density"
  rect 1.1x1.2 smd: 1(-1.05,0) 2(1.05,0)
  silkscreen extent -0.15,-0.5 0.15,0.5
0805_HV [mil] "0805 with 30mil clearance between pads"
  rect 50x63 smd: 1(-40,0) 2(40,0)
  silkscreen extent -74,-40 74,40
1206_180 [mm] "1206_180"
  rect 1.1x1.6 smd: 1(-1.7,0) 2(1.7,0)
  silkscreen extent -0.9,-1 0.9,1
3216-18 [mm] "Based on AVX recommendation in http://www.avx.com/download/software/literature/AVX-Footprint-Library.pdf"
  rrect7% 1.4x1.8 smd: 1(-1.3,0) 2(1.3,0)
  silkscreen extent -1.9,-1.13 0.8,1.12
AssemblyNote [mm] "Assembly Note"
AssemblyNoteLabel [mm] "Assembly Note for PCB Labels"
Bumpon_SJ5003Transparent [mil] "3M Hemispherical Bumpon transparent"
  round 1 on Mech4: 0(0,0)
  silkscreen extent -228,-228 228,228
CAPC0603(1608)100_L [mm] "Chip Capacitor, Body 1.6x0.8mm, Height 1.0mm, IPC High Density"
  rect 0.7x0.9 smd: 1(-0.7,0) 2(0.7,0)
  silkscreen extent -0.05,-0.35 0.05,0.35
CAPC2013X135X45LL10T25 [mm] "Chip Capacitor, 2-Leads, Body 2.00x1.25mm, IPC High Density"
  rect 1x1.3 smd: 1(-0.75,0) 2(0.75,0)
CE_Mark_5mm [mm] "Minimum text height for CE Mark"
CONN_PEC07DAAN [mm] "SULLINS"
  rect 1.65x1.65 hole 1.016 mask+0: 1(-7.62,-1.27)
  round 1.65 hole 1.016 mask+0: 2(-7.62,1.27) 3(-5.08,-1.27) 4(-5.08,1.27) 5(-2.54,-1.27) 6(-2.54,1.27) 7(0,-1.27) 8(0,1.27) 9(2.54,-1.27) 10(2.54,1.27) 11(5.08,-1.27) 12(5.08,1.27) 13(7.62,-1.27) 14(7.62,1.27)
  silkscreen extent -9.99,-2.6 8.89,2.54
CTE_CT3151SP-0 [mm] "Banana Jack Insul Nylon Black, R/A, TH"
  round 2.1 hole 1.6: 1(18.898,-2.54) 1(18.898,2.54) 1(23.978,-2.54) 1(23.978,2.54)
  silkscreen extent 0.44,-6.75 18.02,6.75
CTE_CT3151SP-2 [mm] "Banana Jack Insul Nylon Red, R/A, TH"
  round 2.1 hole 1.6: 1(18.898,-2.54) 1(18.898,2.54) 1(23.978,-2.54) 1(23.978,2.54)
  silkscreen extent 0.44,-6.75 18.02,6.75
D0008A_N [mm] "SOIC, 8-Leads, Body 4.9x3.9mm, Pitch 1.27mm, IPC Medium Density"
  oval 1.45x0.6 smd: 1(-2.725,1.905) 2(-2.725,0.635) 3(-2.725,-0.635) 4(-2.725,-1.905) 5(2.725,-1.905) 6(2.725,-0.635) 7(2.725,0.635) 8(2.725,1.905)
  silkscreen extent -3.3,-2.5 0.9,2.5
DGK0008A_N [mm] "TSOP, 8-Leads, Body 3x3mm, Pitch 0.65mm, IPC Medium Density"
  oval 1.35x0.45 smd: 1(-2.225,0.975) 2(-2.225,0.325) 3(-2.225,-0.325) 4(-2.225,-0.975) 5(2.225,-0.975) 6(2.225,-0.325) 7(2.225,0.325) 8(2.225,0.975)
  silkscreen extent -2.75,-1.55 0.95,1.55
DQJ0008A [mm] "SMD, 8-Leads, Body 5.75x4.9mm"
  rrect39% 0.91x0.51 smd paste-0.05 mask+0: 1(-2.795,1.905) 2(-2.795,0.635) 3(-2.795,-0.635) 4(-2.795,-1.905) 5(2.795,-1.905) 6(2.795,-0.635) 7(2.795,0.635) 8(2.795,1.905)
  rrect8% 1.58x1.25 on Top Paste: 9(-0.38,1.45) 9(-0.38,0) 9(-0.38,-1.45) 9(1.4,1.45) 9(1.4,0) 9(1.4,-1.45)
  rrect3% 3.48x4.47 on Top Solder: 9(0.55,0)
  rrect2% 4.49x4.57 smd paste-2.5 mask+0: 9(1.005,0)
  silkscreen extent -3,-2.6 3,2.6
DRL0005A [mm] "SOTFL, 5-Flat Leads, Body 1.2x1.6x0.6mm, Pitch 0.5mm, TI recommended"
  rrect33% 0.67x0.3 smd: 1(-0.74,0.5) 2(-0.74,0) 3(-0.74,-0.5) 4(0.74,-0.5) 5(0.74,0.5)
  silkscreen extent -0.9,-0.95 0.5,0.95
DRV0006A [mm] "SON, 6-Leads, Body 2x2mm, Pitch 0.65mm, Thermal Pad 1.6x1mm, TI Recommended"
  rrect33% 0.45x0.3 smd: 1(-0.975,0.65) 2(-0.975,0) 3(-0.975,-0.65) 4(0.975,-0.65) 5(0.975,0) 6(0.975,0.65)
  rrect14% 1x0.7 on Top Paste: 7(0,0.45) 7(0,-0.45)
  rrect10% 1x1.6 smd paste-0.5: 7(0,0)
  silkscreen extent -1.05,-1.2 1.05,1.2
FCC_disclaimer [mm]
Fiducial10-20 [mm]
  round 1 smd mask+0: 1(0,0)
  Top Layer keep-out circle w1.178: c0,0 r0.5
FP-691256610002_HDR2-MFG [mm]
  rrect4% 2.45x2.45 hole 1.6 paste-1000 mask+0: 1(-5.08,7.55)
  round 2.45 hole 1.6 paste-1000 mask+0: 1(-5.08,-2.61) 2(5.08,7.55) 2(5.08,-2.61)
  silkscreen extent -11,-9.2 10.21,9.2
FP-C0603C-CF-MFG#1 [mm]
  rect 0.75x0.9 smd paste+0 mask+0: 1(-0.5,0) 2(0.7,0)
  silkscreen extent -0.78,-0.85 0.98,0.85
FP-C0603C-CF-MFG#2 [mm]
  rect 0.75x0.9 smd paste+0 mask+0: 1(-0.6,0) 2(0.6,0)
  silkscreen extent -0.87,-0.85 0.88,0.85
FP-CC0603-DA-MFG [mm]
  rect 0.8x0.9 smd paste+0 mask+0: 1(-0.75,0) 2(0.75,0)
  silkscreen extent -0.85,-0.85 0.85,0.85
FP-CL10-0_1-MFG [mm]
  rect 0.625x0.825 smd paste+0 mask+0: 1(-0.575,0) 2(0.575,0)
  silkscreen extent -0.8,-0.79 0.8,0.79
FP-CL10-IPC_A [mm]
  rect 1.158x1.012 smd paste+0 mask+0: 1(-0.827,0) 2(0.827,0)
  silkscreen extent -1.41,-0.91 1.41,0.91
FP-PR20203VBNN-MFG [mm]
  rect 1.57x1.57 hole 1.02 paste-1000 mask+0: 1(-2.54,0)
  round 1.57 hole 1.02 paste-1000 mask+0: 2(0,0) 3(2.54,0)
  silkscreen extent -4.7,-1.25 3.81,1.25
FP-SMAJ-CA-MFG [mm]
  rect 2.1x1.8 smd paste+0 mask+0: 1(-2.2,0) 2(2.2,0)
  silkscreen extent -2.3,-1.4 2.3,1.39
Fuse_0463 [mm] "SMD, 2-Leads, Body 10.1x3.12mm"
  rrect3% 3.25x3.43 smd: 1(-4.675,0) 2(4.675,0)
  silkscreen extent -2.6,-1.5 2.6,1.5
Harwin_D3082-05 [mm] "Shorting Plug, 10.16mm spacing, TH"
  round 1.8 hole 1.3: 1(-5.08,0) 2(5.08,0)
  silkscreen extent -3.9,-0.53 3.9,0.53
HTSSOP-28-epod [mm]
  rect 1.5x0.45 smd: 1(0,0) 2(0,-0.65) 3(0,-1.3) 4(0,-1.95) 5(0,-2.6) 6(0,-3.25) 7(0,-3.9) 8(0,-4.55) 9(0,-5.2) 10(0,-5.85) 11(0,-6.5) 12(0,-7.15) 13(0,-7.8) 14(0,-8.45) 15(5.8,-8.45) 16(5.8,-7.8) 17(5.8,-7.15) 18(5.8,-6.5) 19(5.8,-5.85) 20(5.8,-5.2) 21(5.8,-4.55) 22(5.8,-3.9) 23(5.8,-3.25) 24(5.8,-2.6) 25(5.8,-1.95) 26(5.8,-1.3) 27(5.8,-0.65) 28(5.8,0)
  rect 2.53x5.8 smd: 29(2.9,-4.225)
  silkscreen extent 1.58,-8.78 4.22,0.33
IEC_Caution_Small [mm]
  silkscreen extent -2.72,-2.36 2.72,2.35
IEC_HotSurface_Small [mm]
  silkscreen extent -2.72,-2.36 2.72,2.35
Keystone5010 [mil] "Keystone Multipurpose loops"
  round 87 hole 63: 1(0,0)
  silkscreen extent -70,-70 70,70
Keystone5011 [mil] "Keystone Multipurpose loops"
  round 87 hole 63: 1(0,0)
  silkscreen extent -70,-70 70,70
Label_650x200 [mil] "Thermal Transfer Label"
  round 1 on Mech13: 0(0,0)
  silkscreen extent -325,-100 325,100
Molex_1051640001 [mm] "Receptacle, USB 2.0, Micro B, 5 Pos, 0.65mm Pitch, R/A, SMT"
  rrect22% 0.45x1.38 smd: 1(1.3,4.11) 2(0.65,4.11) 3(0,4.11) 4(-0.65,4.11) 5(-1.3,4.11)
  rrect7% 1.475x2.1 smd: 6(-2.462,3.75) 11(2.462,3.75)
  rrect100% 1.4x2.1 hole 0.6 slot 1.3 at 90 deg: 7(-3.95,1.45) 10(3.95,1.45)
  rrect7% 1.375x1.9 smd: 8(-0.938,1.45) 9(0.938,1.45)
  silkscreen extent 1.2,5.1 1.4,5.4
MuRata_CSTNR [mm] "SMD, 3-Leads, Body 4.5x2mm, Pitch 1.5mm"
  rrect25% 0.4x2.6 smd: 1(-1.5,0) 2(0,0) 3(1.5,0)
PW0028A_N [mm] "SOP, 28-Leads, Body 9.8x4.5mm, Pitch 0.65mm, IPC Medium Density"
  rrect22% 1.4x0.45 smd: 1(-2.95,4.225) 2(-2.95,3.575) 3(-2.95,2.925) 4(-2.95,2.275) 5(-2.95,1.625) 6(-2.95,0.975) 7(-2.95,0.325) 8(-2.95,-0.325) 9(-2.95,-0.975) 10(-2.95,-1.625) 11(-2.95,-2.275) 12(-2.95,-2.925) 13(-2.95,-3.575) 14(-2.95,-4.225) 15(2.95,-4.225) 16(2.95,-3.575) 17(2.95,-2.925) 18(2.95,-2.275) 19(2.95,-1.625) 20(2.95,-0.975) 21(2.95,-0.325) 22(2.95,0.325) 23(2.95,0.975) 24(2.95,1.625) 25(2.95,2.275) 26(2.95,2.925) 27(2.95,3.575) 28(2.95,4.225)
  silkscreen extent -3.07,-4.9 1.85,5.13
RESC1609X55X30NL10T20 [mm] "Chip Resistor, 2-Leads, Body 1.60x0.85mm, IPC Medium Density"
  rect 0.95x0.95 smd: 1(-0.725,0) 2(0.725,0)
RGC0064B [mm] "VQFN-64"
  rrect42% 0.6x0.24 smd mask+0: 1(-4.4,3.75) 2(-4.4,3.25) 3(-4.4,2.75) 4(-4.4,2.25) 5(-4.4,1.75) 6(-4.4,1.25) 7(-4.4,0.75) 8(-4.4,0.25) 9(-4.4,-0.25) 10(-4.4,-0.75) 11(-4.4,-1.25) 12(-4.4,-1.75) 13(-4.4,-2.25) 14(-4.4,-2.75) 15(-4.4,-3.25) 16(-4.4,-3.75) 33(4.4,-3.75) 34(4.4,-3.25) 35(4.4,-2.75) 36(4.4,-2.25) 37(4.4,-1.75) 38(4.4,-1.25) 39(4.4,-0.75) 40(4.4,-0.25) 41(4.4,0.25) 42(4.4,0.75) 43(4.4,1.25) 44(4.4,1.75) 45(4.4,2.25) 46(4.4,2.75) 47(4.4,3.25) 48(4.4,3.75)
  rrect42% 0.24x0.6 smd mask+0: 17(-3.75,-4.4) 18(-3.25,-4.4) 19(-2.75,-4.4) 20(-2.25,-4.4) 21(-1.75,-4.4) 22(-1.25,-4.4) 23(-0.75,-4.4) 24(-0.25,-4.4) 25(0.25,-4.4) 26(0.75,-4.4) 27(1.25,-4.4) 28(1.75,-4.4) 29(2.25,-4.4) 30(2.75,-4.4) 31(3.25,-4.4) 32(3.75,-4.4) 49(3.75,4.4) 50(3.25,4.4) 51(2.75,4.4) 52(2.25,4.4) 53(1.75,4.4) 54(1.25,4.4) 55(0.75,4.4) 56(0.25,4.4) 57(-0.25,4.4) 58(-0.75,4.4) 59(-1.25,4.4) 60(-1.75,4.4) 61(-2.25,4.4) 62(-2.75,4.4) 63(-3.25,4.4) 64(-3.75,4.4)
  rrect2% 4.25x4.25 smd paste-2.112: 65(0,0)
Samtec_TSM-105-01-x-DV [mm] "Header, 2.54mm, 5x2, SMT"
  rect 3.68x1.27 smd: 1(-2.475,5.08) 2(2.475,5.08) 3(-2.475,2.54) 4(2.475,2.54) 5(-2.475,0) 6(2.475,0) 7(-2.475,-2.54) 8(2.475,-2.54) 9(-2.475,-5.08) 10(2.475,-5.08)
  silkscreen extent -1.65,-6.35 1.65,6.49
Samtec_TSM-108-01-x-DV [mm] "Header, 2.54mm, 8x2, SMT"
  rect 3.68x1.27 smd: 1(-2.475,8.89) 2(2.475,8.89) 3(-2.475,6.35) 4(2.475,6.35) 5(-2.475,3.81) 6(2.475,3.81) 7(-2.475,1.27) 8(2.475,1.27) 9(-2.475,-1.27) 10(2.475,-1.27) 11(-2.475,-3.81) 12(2.475,-3.81) 13(-2.475,-6.35) 14(2.475,-6.35) 15(-2.475,-8.89) 16(2.475,-8.89)
  silkscreen extent -1.65,-10.16 1.65,10.3
SM_RADIAL_E [mm] "8 x 6.2mm:  Panasonic E"
  rect 4x1.6 smd: 1(-3.1,0) 2(3.1,0)
  silkscreen extent -4.25,-4.25 4.25,4.25
SM_RADIAL_G [mm] "10 x 10.2mm:  Panasonic G"
  rect 4.1x2 smd: 1(-4.35,0) 2(4.35,0)
  silkscreen extent -5.35,-5.35 5.35,5.35
SOD-323 [mm] "NXP recommended land pattern"
  rect 0.6x0.6 smd paste-0.05: 1(-1.1,0) 2(1.1,0)
  silkscreen extent -2.06,-0.86 1.53,0.86
Sullins_PxC12SABN [mm] "Header, 2.54 mm, 12x1, TH"
  rect 1.55x1.55 hole 1.016: 1(-13.97,0)
  round 1.55 hole 1.016: 2(-11.43,0) 3(-8.89,0) 4(-6.35,0) 5(-3.81,0) 6(-1.27,0) 7(1.27,0) 8(3.81,0) 9(6.35,0) 10(8.89,0) 11(11.43,0) 12(13.97,0)
  silkscreen extent -15.49,-1.75 15.49,1.33
SW_FSM4JSMA [mm] "Alcoswitch"
  rrect7% 1.4x2.1 smd: 1(2.25,4.55) 2(2.25,-4.55) 3(-2.25,4.55) 4(-2.25,-4.55)
Testpoint_Keystone_Miniature [mil] "Miniature SMT test point"
  rect 135x70 smd: 1(0,0)
  silkscreen extent -78,-46 78,45
TI_Stacked_Overlay_Small [mm]
TP_H045P075 [mm] "TP_H0.45P0.75"
  round 0.75 hole 0.45: 1(0,0)
WE-HCC-1210 [mm] "Inductor, 2-Leads, Body 12.1 x 11.4 mm"
  rect 2.9x5.4 smd: 1(-4.95,0) 2(4.95,0)
  silkscreen extent -6.2,-5.85 6.2,5.85
WEEE_Minimum [mm] "WEEElie bin"
  silkscreen extent 0.56,-1.79 1.38,1.88
WL-SMCW_GREEN [mm] "WURTH"
  rect 0.8x0.8 smd: 1(-0.8,0) 2(0.8,0)
  silkscreen extent -1.9,-0.8 1.2,0.8
WL-SMCW_RED [mm] "WURTH"
  rect 0.8x0.8 smd: 1(-0.8,0) 2(0.8,0)
  silkscreen extent -1.9,-0.8 1.2,0.8
Wurth_61000621121 [mm] "Header, 2.54mm, 3x2, SMT"
  rrect10% 3.1x1 smd: 1(-2.7,2.54) 2(2.7,2.54) 3(-2.7,0) 4(2.7,0) 5(-2.7,-2.54) 6(2.7,-2.54)
Wurth_61301421121 [mm] "Header, 2.54mm, 7x2, TH"
  rrect50% 1.65x1.65 hole 1.1: 1(-1.27,7.62)
  round 1.65 hole 1.1: 2(1.27,7.62) 3(-1.27,5.08) 4(1.27,5.08) 5(-1.27,2.54) 6(1.27,2.54) 7(-1.27,0) 8(1.27,0) 9(-1.27,-2.54) 10(1.27,-2.54) 11(-1.27,-5.08) 12(1.27,-5.08) 13(-1.27,-7.62) 14(1.27,-7.62)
